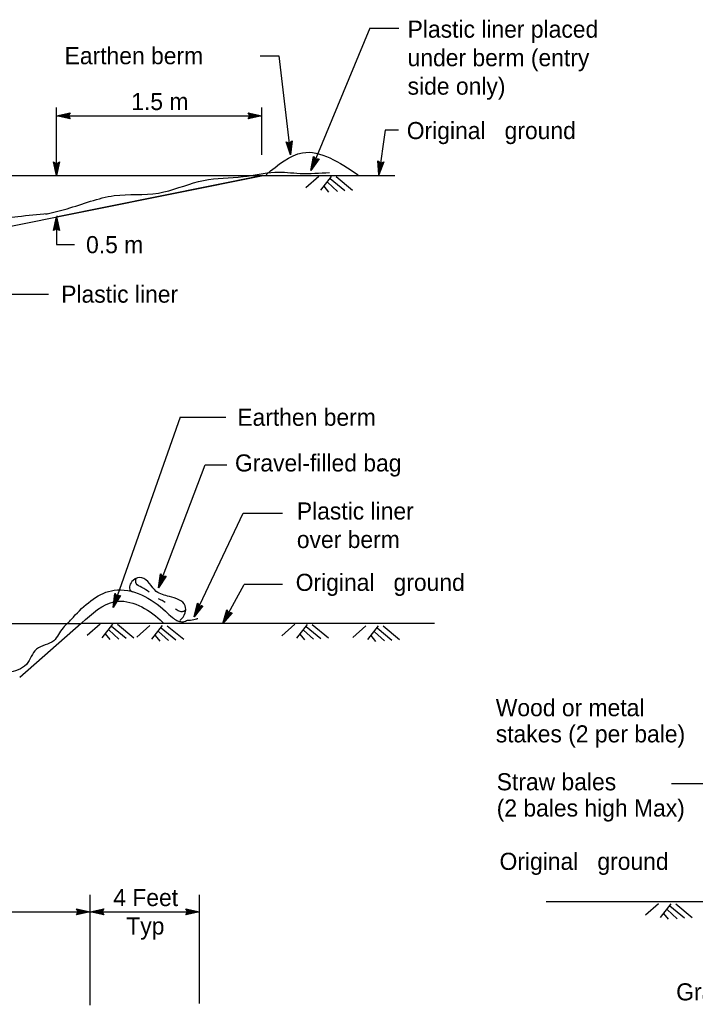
# Model space of a CAD drawing. Extents: x 6707406 to 6714471, y 1868570 to 1872341.
# Drawn here: x 6709143.3 to 6709427.8, y 1869105.8 to 1869521.1 of the extents above; entities that cross this region are included whole.
import ezdxf

# ---------------------------------------------------------------- set-up
doc = ezdxf.new("R2010")
doc.units = 0
for name, color, linetype in [('1 Control', 7, 'Continuous'), ('56 Stg 3 Anno', 7, 'Continuous'), ('57 Undefined', 7, 'Continuous'), ('59 Soundwall Ann', 7, 'Continuous'), ('60 Nongeo Data', 7, 'Continuous')]:
    doc.layers.add(name, color=color, linetype=linetype)

msp = doc.modelspace()

# ---------------------------------------------------------------- linework, layer by layer
at = {"layer": '1 Control'}
for p, q in [((6709267.01, 1869463.37), (6709267.01, 1869463.37)), ((6709269.37, 1869462.4), (6709269.37, 1869462.4)), ((6709265.99, 1869457.56), (6709265.99, 1869457.56)), ((6709202.56, 1869287.55), (6709202.56, 1869287.55)), ((6709204.96, 1869286.64), (6709204.96, 1869286.64)), ((6709183.36, 1869279.3), (6709183.36, 1869279.3)), ((6709201.71, 1869281.71), (6709201.71, 1869281.71)), ((6709185.77, 1869278.45), (6709185.77, 1869278.45)), ((6709218.15, 1869275.23), (6709218.15, 1869275.23)), ((6709182.65, 1869273.45), (6709182.65, 1869273.45)), ((6709220.47, 1869274.13), (6709220.47, 1869274.13)), ((6709230.52, 1869272.38), (6709230.52, 1869272.38)), ((6709232.77, 1869271.16), (6709232.77, 1869271.16)), ((6709216.84, 1869269.47), (6709216.84, 1869269.47)), ((6709228.89, 1869266.71), (6709228.89, 1869266.71))]:
    msp.add_line(p, q, dxfattribs=at)
for points in [[(6709269.37, 1869462.4), (6709265.99, 1869457.56), (6709267, 1869463.38), (6709267.24, 1869463.06), (6709266.49, 1869458.8), (6709268.98, 1869462.34), (6709268.59, 1869462.28), (6709267, 1869460.01), (6709267.48, 1869462.74), (6709267.71, 1869462.42), (6709267.51, 1869461.24), (6709268.2, 1869462.22), (6709267.89, 1869462.18), (6709267, 1869463.38), (6709267.89, 1869462.18)], [(6709204.96, 1869286.64), (6709201.71, 1869281.71), (6709202.56, 1869287.55), (6709202.81, 1869287.24), (6709202.18, 1869282.96), (6709204.57, 1869286.57), (6709204.18, 1869286.5), (6709202.65, 1869284.19), (6709203.05, 1869286.92), (6709203.3, 1869286.61), (6709203.13, 1869285.43), (6709203.79, 1869286.43), (6709203.48, 1869286.38), (6709202.56, 1869287.55), (6709203.48, 1869286.38)], [(6709185.77, 1869278.45), (6709182.65, 1869273.45), (6709183.35, 1869279.3), (6709183.61, 1869279), (6709183.09, 1869274.71), (6709185.38, 1869278.37), (6709185, 1869278.29), (6709183.53, 1869275.95), (6709183.86, 1869278.69), (6709184.11, 1869278.38), (6709183.97, 1869277.2), (6709184.61, 1869278.22), (6709184.3, 1869278.15), (6709183.35, 1869279.3), (6709184.3, 1869278.15)], [(6709220.47, 1869274.13), (6709216.84, 1869269.47), (6709218.15, 1869275.23), (6709218.37, 1869274.9), (6709217.41, 1869270.68), (6709220.07, 1869274.1), (6709219.68, 1869274.06), (6709217.98, 1869271.87), (6709218.59, 1869274.57), (6709218.81, 1869274.24), (6709218.55, 1869273.07), (6709219.28, 1869274.02), (6709218.98, 1869273.99), (6709218.15, 1869275.23), (6709218.98, 1869273.99)], [(6709232.77, 1869271.16), (6709228.89, 1869266.71), (6709230.52, 1869272.38), (6709230.72, 1869272.04), (6709229.53, 1869267.88), (6709232.37, 1869271.14), (6709231.98, 1869271.12), (6709230.16, 1869269.04), (6709230.92, 1869271.7), (6709231.12, 1869271.35), (6709230.79, 1869270.2), (6709231.58, 1869271.11), (6709231.27, 1869271.1), (6709230.52, 1869272.38), (6709231.27, 1869271.1)]]:
    msp.add_lwpolyline(points, close=True, dxfattribs=at)
msp.add_spline([(6709209.29, 1869267.99), (6709211.08, 1869267.44), (6709212.61, 1869267.44), (6709213.63, 1869267.95), (6709215.32, 1869268.12), (6709217.86, 1869268.63), (6709218.37, 1869268.8)], degree=3, dxfattribs=at)
at = {"layer": '56 Stg 3 Anno'}
for p, q in [((6709290.72, 1869517.49), (6709265.99, 1869457.56)), ((6709290.72, 1869517.49), (6709302.98, 1869517.49)), ((6709244.61, 1869505.89), (6709252.38, 1869505.89)), ((6709252.38, 1869505.89), (6709257.43, 1869464.09)), ((6709158.78, 1869455.4), (6709158.78, 1869484.01)), ((6709245.32, 1869464.09), (6709245.32, 1869484.01)), ((6709158.78, 1869480.58), (6709164.54, 1869481.86)), ((6709158.78, 1869480.58), (6709245.32, 1869480.58)), ((6709164.54, 1869479.29), (6709158.78, 1869480.58)), ((6709158.78, 1869480.58), (6709158.78, 1869480.58)), ((6709164.34, 1869479.64), (6709160.11, 1869480.58)), ((6709160.12, 1869480.58), (6709164.32, 1869481.51)), ((6709161.44, 1869480.58), (6709164.15, 1869481.18)), ((6709164.11, 1869479.98), (6709161.44, 1869480.58)), ((6709162.76, 1869480.58), (6709163.92, 1869480.83)), ((6709163.94, 1869480.31), (6709162.76, 1869480.58)), ((6709164.54, 1869481.86), (6709163.78, 1869480.58)), ((6709163.78, 1869480.58), (6709164.54, 1869479.29)), ((6709164.54, 1869481.86), (6709164.54, 1869481.86)), ((6709164.54, 1869479.29), (6709164.54, 1869479.29)), ((6709240.33, 1869480.58), (6709239.56, 1869481.87)), ((6709239.56, 1869481.87), (6709239.56, 1869481.87)), ((6709239.56, 1869481.87), (6709245.32, 1869480.58)), ((6709245.32, 1869480.58), (6709239.56, 1869479.3)), ((6709239.56, 1869479.3), (6709240.33, 1869480.58)), ((6709239.56, 1869479.3), (6709239.56, 1869479.3)), ((6709239.77, 1869481.52), (6709243.99, 1869480.58)), ((6709243.98, 1869480.58), (6709239.78, 1869479.65)), ((6709242.67, 1869480.58), (6709239.95, 1869479.98)), ((6709239.99, 1869481.18), (6709242.67, 1869480.58)), ((6709240.16, 1869480.85), (6709241.34, 1869480.58)), ((6709241.34, 1869480.58), (6709240.18, 1869480.33)), ((6709245.32, 1869480.58), (6709245.32, 1869480.58)), ((6709297.29, 1869474.56), (6709294.59, 1869455.69)), ((6709302.88, 1869474.56), (6709297.29, 1869474.56)), ((6709257.43, 1869464.09), (6709255.47, 1869469.65)), ((6709255.47, 1869469.65), (6709255.47, 1869469.65)), ((6709255.47, 1869469.65), (6709256.83, 1869469.04)), ((6709257.26, 1869465.41), (6709255.84, 1869469.47)), ((6709257.11, 1869466.72), (6709256.19, 1869469.34)), ((6709256.95, 1869468.04), (6709256.56, 1869469.16)), ((6709256.83, 1869469.04), (6709258.01, 1869469.96)), ((6709257.07, 1869469.24), (6709256.95, 1869468.04)), ((6709257.38, 1869469.45), (6709257.11, 1869466.72)), ((6709257.7, 1869469.71), (6709257.27, 1869465.4)), ((6709258.01, 1869469.96), (6709257.43, 1869464.09)), ((6709258.01, 1869469.96), (6709258.01, 1869469.96)), ((6709257.43, 1869464.09), (6709257.43, 1869464.09)), ((6709158.78, 1869455.4), (6709157.51, 1869461.16)), ((6709157.51, 1869461.16), (6709157.51, 1869461.16)), ((6709157.51, 1869461.16), (6709158.78, 1869460.39)), ((6709158.78, 1869456.74), (6709157.85, 1869460.94)), ((6709158.79, 1869458.05), (6709158.18, 1869460.77)), ((6709158.79, 1869459.38), (6709158.53, 1869460.54)), ((6709158.78, 1869460.39), (6709160.07, 1869461.16)), ((6709160.07, 1869461.16), (6709158.78, 1869455.4)), ((6709159.73, 1869460.95), (6709158.78, 1869456.73)), ((6709159.38, 1869460.73), (6709158.79, 1869458.05)), ((6709159.05, 1869460.56), (6709158.79, 1869459.38)), ((6709160.07, 1869461.16), (6709160.07, 1869461.16)), ((6709294.59, 1869455.69), (6709294.2, 1869461.57)), ((6709294.2, 1869461.57), (6709294.2, 1869461.57)), ((6709294.2, 1869461.57), (6709295.34, 1869460.62)), ((6709294.79, 1869457.01), (6709294.5, 1869461.3)), ((6709296.73, 1869461.18), (6709294.59, 1869455.69)), ((6709296.36, 1869461.03), (6709294.79, 1869456.99)), ((6709294.99, 1869458.31), (6709294.81, 1869461.08)), ((6709295.99, 1869460.86), (6709294.99, 1869458.31)), ((6709295.19, 1869459.62), (6709295.11, 1869460.8)), ((6709295.63, 1869460.74), (6709295.19, 1869459.62)), ((6709295.34, 1869460.62), (6709296.73, 1869461.18)), ((6709296.73, 1869461.18), (6709296.73, 1869461.18)), ((6709158.78, 1869455.4), (6709158.78, 1869455.4)), ((6709294.59, 1869455.69), (6709294.59, 1869455.69)), ((6709157.5, 1869432.22), (6709158.78, 1869437.98)), ((6709158.78, 1869437.98), (6709158.78, 1869426.29)), ((6709158.78, 1869437.98), (6709158.78, 1869437.98)), ((6709158.78, 1869437.98), (6709160.06, 1869432.22)), ((6709158.78, 1869432.98), (6709157.5, 1869432.22)), ((6709157.84, 1869432.42), (6709158.78, 1869436.65)), ((6709158.18, 1869432.65), (6709158.78, 1869435.32)), ((6709158.52, 1869432.82), (6709158.78, 1869434)), ((6709158.78, 1869435.32), (6709159.38, 1869432.61)), ((6709158.78, 1869434), (6709159.04, 1869432.84)), ((6709160.06, 1869432.22), (6709158.78, 1869432.98)), ((6709158.79, 1869436.64), (6709159.72, 1869432.44)), ((6709157.5, 1869432.22), (6709157.5, 1869432.22)), ((6709160.06, 1869432.22), (6709160.06, 1869432.22)), ((6709158.78, 1869426.29), (6709166.42, 1869426.29)), ((6709127.18, 1869405.43), (6709155.5, 1869405.43)), ((6709210.84, 1869353.56), (6709182.65, 1869273.45)), ((6709210.84, 1869353.56), (6709230.11, 1869353.56)), ((6709201.71, 1869281.71), (6709221.36, 1869333.46)), ((6709221.36, 1869333.46), (6709230.52, 1869333.46)), ((6709216.84, 1869269.47), (6709237.5, 1869313.21)), ((6709237.5, 1869313.21), (6709253.96, 1869313.21)), ((6709228.89, 1869266.71), (6709237.82, 1869283.16)), ((6709254, 1869283.16), (6709237.82, 1869283.16)), ((6709493.42, 1869199.11), (6709417.73, 1869199.11)), ((6709173.02, 1869105.81), (6709173.02, 1869152.41)), ((6709219.07, 1869131.11), (6709219.07, 1869152.41)), ((6709168.03, 1869145.21), (6709167.26, 1869146.5)), ((6709167.26, 1869146.5), (6709167.26, 1869146.5)), ((6709167.26, 1869146.5), (6709173.02, 1869145.21)), ((6709173.02, 1869145.21), (6709178.78, 1869146.49)), ((6709178.78, 1869146.49), (6709178.02, 1869145.21)), ((6709178.78, 1869146.49), (6709178.78, 1869146.49)), ((6709214.07, 1869145.21), (6709213.31, 1869146.5)), ((6709213.31, 1869146.5), (6709213.31, 1869146.5)), ((6709213.31, 1869146.5), (6709219.07, 1869145.21)), ((6708957.34, 1869145.21), (6709173.02, 1869145.21)), ((6709173.02, 1869145.21), (6709167.26, 1869143.93)), ((6709167.26, 1869143.93), (6709168.03, 1869145.21)), ((6709167.26, 1869143.93), (6709167.26, 1869143.93)), ((6709167.47, 1869146.15), (6709171.7, 1869145.21)), ((6709171.69, 1869145.21), (6709167.49, 1869144.28)), ((6709170.37, 1869145.21), (6709167.66, 1869144.61)), ((6709167.7, 1869145.81), (6709170.37, 1869145.21)), ((6709167.87, 1869145.48), (6709169.05, 1869145.21)), ((6709169.05, 1869145.21), (6709167.89, 1869144.96)), ((6709173.02, 1869145.21), (6709219.07, 1869145.21)), ((6709173.02, 1869145.21), (6709173.02, 1869145.21)), ((6709178.78, 1869143.92), (6709173.02, 1869145.21)), ((6709173.02, 1869145.21), (6709173.02, 1869145.21)), ((6709178.58, 1869144.27), (6709174.35, 1869145.21)), ((6709174.36, 1869145.21), (6709178.56, 1869146.14)), ((6709175.68, 1869145.21), (6709178.39, 1869145.81)), ((6709178.35, 1869144.61), (6709175.68, 1869145.21)), ((6709177, 1869145.21), (6709178.16, 1869145.46)), ((6709178.18, 1869144.94), (6709177, 1869145.21)), ((6709178.02, 1869145.21), (6709178.78, 1869143.92)), ((6709178.78, 1869143.92), (6709178.78, 1869143.92)), ((6709219.07, 1869145.21), (6709213.31, 1869143.93)), ((6709213.31, 1869143.93), (6709214.07, 1869145.21)), ((6709213.31, 1869143.93), (6709213.31, 1869143.93)), ((6709213.51, 1869146.15), (6709217.74, 1869145.21)), ((6709217.73, 1869145.21), (6709213.53, 1869144.28)), ((6709216.41, 1869145.21), (6709213.7, 1869144.61)), ((6709213.74, 1869145.81), (6709216.41, 1869145.21)), ((6709213.91, 1869145.48), (6709215.09, 1869145.21)), ((6709215.09, 1869145.21), (6709213.93, 1869144.96)), ((6709219.07, 1869145.21), (6709219.07, 1869145.21)), ((6709219.07, 1869106.58), (6709219.07, 1869133.32))]:
    msp.add_line(p, q, dxfattribs=at)
at = {"layer": '59 Soundwall Ann'}
for p, q in [((6709269.3, 1869455.02), (6709263.82, 1869450.15)), ((6709274.5, 1869454.98), (6709269.98, 1869449.24)), ((6709274.05, 1869454.12), (6709280.24, 1869449.03)), ((6709276.6, 1869454.96), (6709283.53, 1869449.26)), ((6709271.42, 1869450.89), (6709273.4, 1869448.46)), ((6709272.92, 1869452.54), (6709277.15, 1869448.69)), ((6709177.22, 1869266.44), (6709171.74, 1869261.56)), ((6709182.41, 1869266.4), (6709177.9, 1869260.65)), ((6709180.84, 1869263.95), (6709185.06, 1869260.11)), ((6709181.97, 1869265.54), (6709188.16, 1869260.44)), ((6709184.52, 1869266.38), (6709191.44, 1869260.68)), ((6709198.19, 1869265.8), (6709192.71, 1869260.93)), ((6709203.38, 1869265.77), (6709198.87, 1869260.02)), ((6709201.81, 1869263.32), (6709206.03, 1869259.47)), ((6709202.94, 1869264.9), (6709209.13, 1869259.81)), ((6709205.49, 1869265.74), (6709212.41, 1869260.04)), ((6709259.2, 1869266.34), (6709253.72, 1869261.46)), ((6709264.39, 1869266.3), (6709259.87, 1869260.55)), ((6709262.81, 1869263.85), (6709267.04, 1869260)), ((6709263.94, 1869265.44), (6709270.13, 1869260.34)), ((6709266.5, 1869266.28), (6709273.42, 1869260.58)), ((6709289.06, 1869265.7), (6709283.58, 1869260.83)), ((6709294.26, 1869265.67), (6709289.74, 1869259.92)), ((6709292.68, 1869263.22), (6709296.91, 1869259.37)), ((6709293.81, 1869264.8), (6709300, 1869259.71)), ((6709296.36, 1869265.64), (6709303.29, 1869259.94)), ((6709179.34, 1869262.3), (6709181.32, 1869259.87)), ((6709200.31, 1869261.67), (6709202.29, 1869259.24)), ((6709261.31, 1869262.2), (6709263.29, 1869259.77)), ((6709291.18, 1869261.57), (6709293.16, 1869259.14)), ((6709412.31, 1869148.59), (6709406.83, 1869143.72)), ((6709417.5, 1869148.55), (6709412.98, 1869142.81)), ((6709417.05, 1869147.69), (6709423.24, 1869142.6)), ((6709419.61, 1869148.53), (6709426.53, 1869142.83)), ((6709414.42, 1869144.46), (6709416.4, 1869142.03)), ((6709415.92, 1869146.11), (6709420.15, 1869142.26))]:
    msp.add_line(p, q, dxfattribs=at)
at = {"layer": '60 Nongeo Data'}
for p, q in [((6708926.44, 1869455.4), (6709246.42, 1869455.4)), ((6709079.54, 1869422.13), (6709245.91, 1869455.4)), ((6709159.31, 1869438.15), (6709245.73, 1869455.6)), ((6709245.93, 1869455.42), (6709301.24, 1869455.4)), ((6709159.31, 1869438.15), (6709158.84, 1869438.19)), ((6709100.59, 1869266.71), (6709168.62, 1869266.71)), ((6709169.25, 1869266.71), (6709143.34, 1869243.93)), ((6709318.02, 1869266.71), (6709169.25, 1869266.71)), ((6709365.05, 1869149.57), (6709494.96, 1869149.57))]:
    msp.add_line(p, q, dxfattribs=at)
for points in [[(6709247.09, 1869455.75), (6709262.42, 1869465), (6709285.84, 1869455.72)], [(6709154.27, 1869439.18), (6709163.26, 1869441.4), (6709183.16, 1869446.94), (6709201.75, 1869448.04), (6709204.06, 1869448.49), (6709220.76, 1869453.35), (6709237.4, 1869454.94), (6709250.83, 1869456.82), (6709261.39, 1869456.32), (6709273.82, 1869456.69)], [(6709155.03, 1869439.22), (6709142.61, 1869438.01), (6709137.51, 1869437.25), (6709118.63, 1869431.78), (6709098.86, 1869429.66), (6709092.64, 1869427.99), (6709077.2, 1869424.09), (6709067.17, 1869423.66), (6709051.11, 1869425.1), (6709040.55, 1869425.74), (6709027.92, 1869424.04), (6709018.17, 1869423.86)], [(6709210.81, 1869267.86), (6709213.02, 1869271.09), (6709212.98, 1869274.12), (6709206.38, 1869278.03), (6709200.85, 1869280.2), (6709194.76, 1869285.94), (6709191.05, 1869284.82), (6709189.91, 1869280.59), (6709190.88, 1869279.96)], [(6709197.88, 1869279.91), (6709194.78, 1869281.84), (6709192.4, 1869283.55), (6709192.34, 1869285.52)], [(6709163.52, 1869266.68), (6709166.75, 1869270.26), (6709183.08, 1869280.71), (6709204.79, 1869271.86), (6709207.63, 1869269.23), (6709209.48, 1869267.86)], [(6709169.21, 1869266.71), (6709169.5, 1869266.97), (6709183.52, 1869275.93), (6709202.46, 1869268.22), (6709204, 1869266.75)], [(6709204.59, 1869275.5), (6709202.89, 1869276.56), (6709201.71, 1869277.09)], [(6709213.39, 1869272.37), (6709212.09, 1869271.67), (6709210.47, 1869271.83), (6709208.92, 1869272.79)], [(6709163.61, 1869266.78), (6709161.57, 1869264.84), (6709157.64, 1869259.41), (6709150.39, 1869255.79), (6709146.16, 1869249.46), (6709138.31, 1869246.15), (6709117.17, 1869249.16), (6709106.9, 1869247.35), (6709095.12, 1869247.35), (6709084.24, 1869249.16), (6709070.65, 1869246.75), (6709059.78, 1869246.75), (6709051.02, 1869249.16), (6709041.66, 1869248.56), (6709034.11, 1869246.75), (6709023.53, 1869246.15), (6709014.78, 1869248.26), (6709003.9, 1869249.16), (6708994.24, 1869246.75), (6708986.99, 1869246.75), (6708979.74, 1869247.96), (6708976.12, 1869252.18), (6708967.66, 1869258.2), (6708963.43, 1869265.14), (6708959.5, 1869265.74), (6708958.51, 1869266.68)]]:
    msp.add_spline(points, degree=3, dxfattribs=at)

# ---------------------------------------------------------------- texts
at = {"layer": '57 Undefined'}
for s, height, p in [('Plastic liner placed ', 7.2002, (6709306.67, 1869513.47)), ('Earthen berm', 7.2002, (6709162.25, 1869502.29)), ('under berm (entry ', 7.2002, (6709306.67, 1869501.47)), ('side only)', 7.2, (6709306.67, 1869489.47)), ('1.5 m', 7.2, (6709190.31, 1869482.98)), ('Original   ground', 7.2002, (6709306.32, 1869470.75)), ('0.5 m', 7.2, (6709171.28, 1869422.69)), ('Plastic liner', 7.2002, (6709160.82, 1869401.83)), ('Earthen berm', 7.2002, (6709234.96, 1869349.96)), ('Gravel-filled bag', 7.2002, (6709233.98, 1869330.71)), ('Plastic liner', 7.2002, (6709260.03, 1869310.46)), ('over berm', 7.2, (6709260.03, 1869298.46)), ('Original   ground', 7.2002, (6709259.55, 1869280.41)), ('Wood or metal ', 7.2002, (6709343.8, 1869227.61)), ('stakes (2 per bale)', 7.2002, (6709343.8, 1869216.57)), ('Straw bales', 7.2002, (6709344.19, 1869196.38)), ('(2 bales high Max)', 7.2002, (6709344.19, 1869185.34)), ('Original   ground', 7.2002, (6709345.38, 1869162.87)), ('4 Feet', 7.2, (6709182.74, 1869147.61)), ('Typ', 7.2, (6709188.22, 1869135.61)), ('Gravel-filled', 7.2002, (6709419.75, 1869107.87))]:
    msp.add_text(s, height=height, dxfattribs=at).set_placement(p)

doc.saveas('drawing.dxf')
